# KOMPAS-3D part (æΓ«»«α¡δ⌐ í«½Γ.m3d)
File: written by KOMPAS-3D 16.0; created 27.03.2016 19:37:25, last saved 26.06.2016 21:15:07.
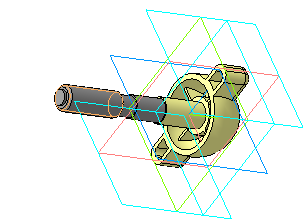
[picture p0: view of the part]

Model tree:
1. Эскиз:1
2. Операция вращения:1
     Угол 1 = 360
3. Оболочка:2
     Толщина стенки 2 = 2
4. Смещенная плоскость:1
     Расстояние = 12
5. Эскиз:4
6. Операция выдавливания:1
     Расстояние 1 = 8
7. Эскиз:5
8. Операция выдавливания:2
     Расстояние 1 = 10.3474
9. Эскиз:6
10. Операция выдавливания:3
     Расстояние 1 = 10.3474
11. Операция выдавливания:4
     Расстояние 1 = 0.347362
12. Операция выдавливания:5
     Расстояние 1 = 0.347362
13. Эскиз:7
14. Операция выдавливания:6
     Расстояние 1 = 8
15. Смещенная плоскость:2
     Расстояние = 25
16. Эскиз:8
17. Операция выдавливания:7
     Расстояние 1 = 8; Расстояние 2 = 12.8845
18. Скругление:1
     Радиус = 3
19. Смещенная плоскость:3
     Расстояние = 25
20. Эскиз:10
21. Операция выдавливания:8
     Расстояние 1 = 12.8845
22. Скругление:2
     Радиус = 3
23. Эскиз:11
24. Вырезать элемент выдавливания:3
     Расстояние 1 = 10
25. Скругление:3
     Радиус = 2
26. Скругление:4
     Радиус = 2
27. Эскиз:12
28. Операция выдавливания:9
     Расстояние 1 = 18; На расстояние 1 = 18
29. Эскиз:14
30. Операция вращения:2
     Угол 1 = 360
31. Фаска:2
     Угол = 45; Длина 1 = 1; Длина 2 = 1
32. Фаска:3
     Угол = 45; Длина 1 = 1; Длина 2 = 1
33. Условное изображение резьбы:2  (labels: E:\Sys\Thread\cil0_8724-2002 fine.xml; M10x1)
     Длина резьбы = 24.5413; Шаг резьбы = 1; Номинальный диаметр резьбы = 10
34. Подгонка:1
